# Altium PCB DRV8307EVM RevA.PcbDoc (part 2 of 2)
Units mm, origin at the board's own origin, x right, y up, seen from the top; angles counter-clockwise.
Board outline 87.73 x 75 mm, 2 copper layers (Top Layer, Bottom Layer), stack 1.575 mm thick; 84 components, 57 nets, 289 pads, 360 vias.
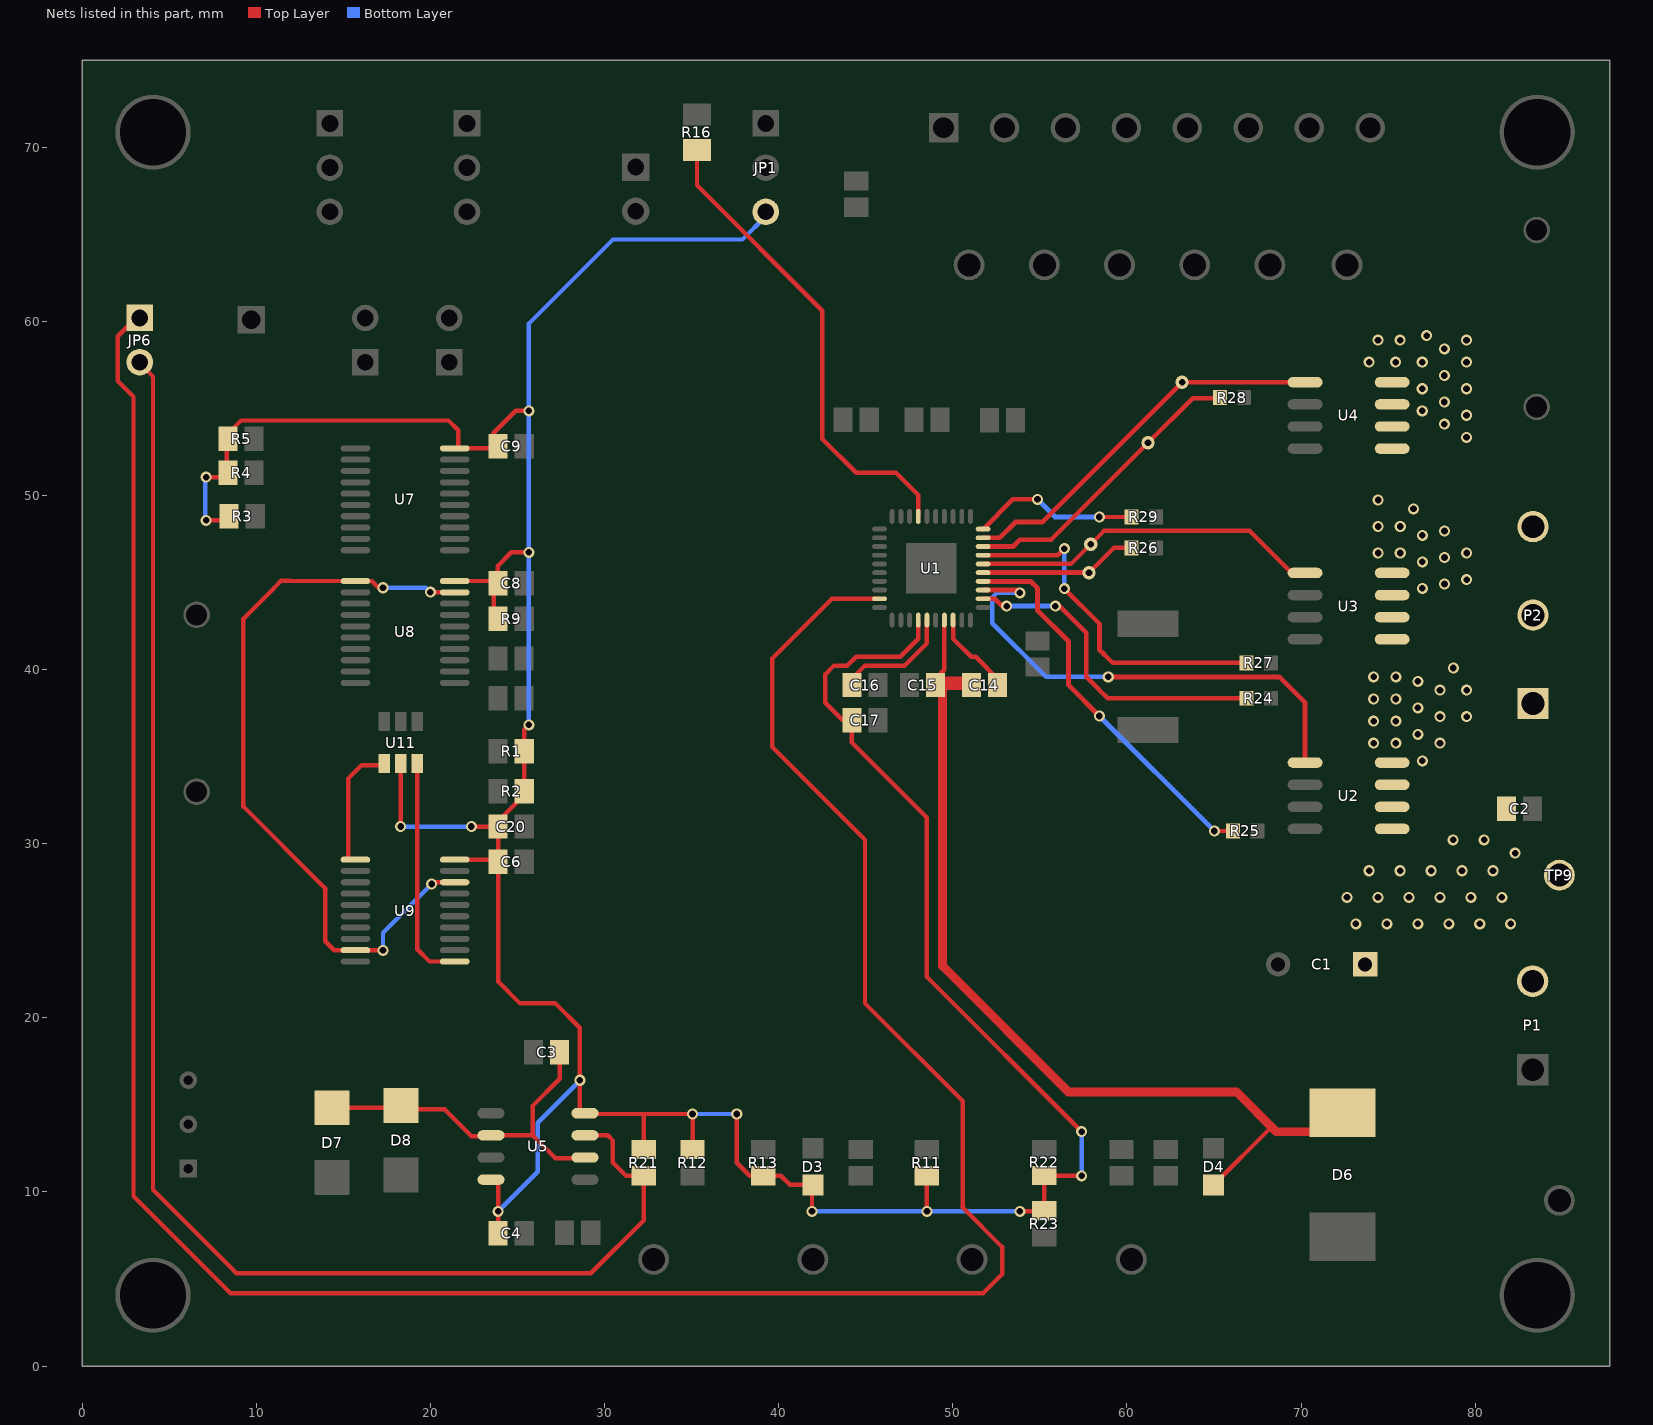
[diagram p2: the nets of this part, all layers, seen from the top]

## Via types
v1: diameter 0.635, hole 0.381, Top Layer to Bottom Layer, tented both sides, 350 vias
v2: diameter 0.635, hole 0.381, Top Layer to Bottom Layer, tented bottom, 5 vias
v3: diameter 0.762, hole 0.381, Top Layer to Bottom Layer, tented bottom, 4 vias
v4: diameter 0.635/0.635 (per signal layer), hole 0.381, Top Layer to Bottom Layer, tented both sides, 1 vias

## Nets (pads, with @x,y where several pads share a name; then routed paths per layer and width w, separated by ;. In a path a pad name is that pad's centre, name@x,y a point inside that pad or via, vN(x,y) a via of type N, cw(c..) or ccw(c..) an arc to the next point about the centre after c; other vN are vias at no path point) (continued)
NetU8_1: U8.1 U8.19 U9.9 U9.18 | length 43.9
  Top Layer w0.254: 13.959,27.432 13.959,24.395 14.467,23.887 U9.9@15.692,23.887 17.261,23.887 v1(17.272,23.876) ; 13.959,27.435 9.258,32.136 9.258,42.926 11.036,44.704 11.036,44.718 11.416,45.098 11.952,45.098 11.961,45.089 U8.1@15.692,45.089 16.633,45.089 17.018,44.704 v1(17.272,44.704) ; v1(19.99,44.45) 21.381,44.45 U8.19@21.392,44.439 ; v1(20.066,27.686) 20.167,27.787 U9.18@21.392,27.787
  Bottom Layer w0.254: v1@17.018,44.704 19.736,44.704 v1(19.99,44.45) ; v1(17.272,23.876) 17.272,24.892 v1(20.066,27.686)
NetU9_1: U9.1 U11.4 | length 7.1
  Top Layer w0.254: U9.1@15.279,29.087 15.279,33.742 16.041,34.505 17.233,34.505 U11.4@17.338,34.61
NetU9_11: U9.11 U11.6 | length 13.1
  Top Layer w0.254: U11.6@19.238,34.614 19.238,23.942 19.943,23.237 U9.11@21.392,23.237
PWM: JP6.1 U1.19 | length 152.4
  Top Layer w0.254: JP6.1@3.163,60.272 2.032,59.141 2.032,56.583 2.946,55.669 2.946,9.761 8.519,4.188 51.741,4.188 52.832,5.279 52.832,6.846 50.58,9.098 50.58,15.206 44.958,20.828 44.958,30.226 39.624,35.56 39.624,40.64 43.056,44.072 U1.19@45.791,44.072
PWM_X: JP6.2 R21.1 U5.7 | length 87.4
  Top Layer w0.254: JP6.2@3.163,57.732 4.064,56.83 4.064,10.126 8.856,5.334 29.21,5.334 32.258,8.382 R21.1@32.258,10.934 31.23,10.934 30.48,11.684 30.48,12.954 30.183,13.251 U5.7@28.565,13.251
THRES: C3.2 D7.1 D8.2 U5.2 U5.6 | length 21.1
  Top Layer w0.254: D7.1@14.349,14.838 18.335,14.838 18.433,14.74 20.82,14.74 22.352,13.208 U5.2@23.622,13.208 ; U5.2@23.765,13.251 25.865,13.251 ; C3.2@27.432,18.288 27.432,16.51 25.865,14.943 25.865,13.251 ; U5.6@28.702,11.938 27.178,11.938 25.865,13.251
U: P2.1 U1.33 U2.1 U2.5 U2.6 | length 28.6
  Top Layer w0.254: v1@53.692,44.572 v1(53.854,44.41)
  Top Layer w0.279: U1.33@51.741,44.572 v1@53.692,44.572 ; v2(58.928,39.584) 68.743,39.584 70.234,38.093 U2.1@70.234,34.662
  Bottom Layer w0.254: v1(53.854,44.41) 52.538,44.41 52.266,44.138 52.266,42.672 55.354,39.584 v2(58.928,39.584)
UHS_GATE: R24.1 U1.32 | length 19
  Top Layer w0.254: v1@52.838,43.648 v1(53.092,43.648) ; 58.403,38.845 58.894,38.354 R24.1@66.864,38.354
  Top Layer w0.279: U1.32@51.741,44.072 52.414,44.072 v1@52.838,43.648 ; v2(55.886,43.648) 56.14,43.648 57.664,42.124 57.664,39.584 58.403,38.845
  Bottom Layer w0.279: v1(53.092,43.648) v2(55.886,43.648)
ULS_GATE: R25.1 U1.34 | length 22.3
  Top Layer w0.254: v1(65.024,30.734) R25.1@66.102,30.734
  Top Layer w0.279: U1.34@51.741,45.072 54.462,45.072 54.87,44.664 54.87,43.394 56.648,41.616 56.648,39.11 v2(58.42,37.338)
  Bottom Layer w0.279: v2(58.42,37.338) v1@64.906,30.852
V: P2.2 U1.36 U3.1 U3.5 U3.6 | length 20.3
  Top Layer w0.254: U1.36@51.741,46.072 56.786,46.072 58.68,47.966 67.062,47.966 69.475,45.553 U3.1@70.234,45.553
  other v3: 57.918,47.204
VCP: C14.2 U1.28 | length 4.6
  Top Layer w0.254: U1.28@50.016,42.847 50.016,41.778 51.052,40.742 51.31,40.742 C14.2@52.614,39.438
VHS_GATE: R26.1 U1.35 | length 9.1
  Top Layer w0.254: v3(57.823,45.572) 59.241,46.99 R26.1@60.26,46.99
  Top Layer w0.279: U1.35@51.741,45.572 v3(57.823,45.572)
VINT: C16.2 U1.25 | length 6.9
  Top Layer w0.254: C16.2@43.902,39.184 44.951,40.234 47.242,40.234 48.516,41.508 U1.25@48.516,42.847
VLS_GATE: R27.1 U1.37 | length 20.2
  Top Layer w0.254: v2(56.407,44.65) 58.42,42.638 ; 58.694,40.874 59.182,40.386 R27.1@66.864,40.386
  Top Layer w0.279: U1.37@51.741,46.572 56.029,46.572 v1(56.407,46.95) ; 58.42,42.638 58.42,41.148 58.694,40.874
  Bottom Layer w0.254: v2(56.407,44.65) v1(56.407,46.95)
VM: C1.1 C2.1 C14.1 C15.1 D4.1 D6.2 P1.2 TP9.1 U1.27 U2.7 U2.8 U3.7 U3.8 U4.7 U4.8 | length 52.6
  Top Layer w0.254: C15.1@49.058,39.534 49.516,39.992 U1.27@49.516,42.847 ; C15.1@49.414,38.895 49.091,39.218 C15.1@49.414,39.541 ; D4.1@64.979,10.409 68.306,13.736
  Top Layer w0.508: C15.1@49.414,38.895 49.414,22.976 56.642,15.748 66.294,15.748 68.58,13.462 D6.2@71.12,13.462
  Top Layer w0.762: C15.1@49.091,39.218 C14.1@51.014,39.218
  other v1: 73.152,25.4 74.93,25.4 76.708,25.4 78.486,25.4 80.264,25.4 82.042,25.4 72.644,26.924 74.422,26.924 76.2,26.924 77.978,26.924 79.756,26.924 81.534,26.924 73.914,28.448 75.692,28.448 77.47,28.448 79.248,28.448 81.026,28.448 82.296,29.464 78.74,30.226 80.518,30.226 76.968,34.758 74.174,35.774 75.444,35.774 77.984,35.774 76.714,36.282 74.174,37.044 75.444,37.044 77.984,37.298 79.508,37.298 76.714,37.806 74.174,38.314 75.444,38.314 77.984,38.822 79.508,38.822 76.714,39.33 74.174,39.584 75.444,39.584 78.746,40.092 76.968,44.664 78.238,44.918 79.508,45.172 76.968,46.188 78.238,46.442 74.428,46.696 75.698,46.696 79.508,46.696 76.968,47.712 78.238,47.966 74.428,48.22 75.698,48.22 76.46,49.236 74.428,49.744 79.502,53.34 78.232,54.102 79.502,54.61 76.962,54.864 78.232,55.372 76.962,56.134 79.502,56.134 78.232,56.896 73.914,57.658 75.438,57.658 76.962,57.658 79.502,57.658 78.232,58.42 74.422,58.928 75.692,58.928 79.502,58.928 77.216,59.182
VREG: C4.2 C6.2 C8.2 C9.2 C17.2 C20.1 D3.1 JP1.3 R1.2 R2.2 R3.2 R4.2 R5.2 R9.2 R11.2 R12.2 R13.2 R21.2 R22.2 R23.2 U1.24 U5.4 U5.8 U7.20 U8.20 U9.20 U11.5 | length 209.3
  Top Layer w0.254: v1(7.112,48.573) 8.29,48.573 R3.2@8.374,48.657 ; v4(7.112,51.054) R4.2@8.311,51.054 ; R5.2@8.311,53.269 R4.2@8.311,51.054 ; R5.2@8.311,53.28 8.311,53.497 9.124,54.31 21.036,54.31 21.59,53.757 U7.20@21.59,52.832 ; R4.2@8.382,51.054 R4.2@8.311,51.054 ; v1(18.288,30.988) U11.5@18.288,34.614 ; U9.20@21.392,29.087 23.757,29.087 C6.2@23.888,28.956 ; U8.20@21.392,45.089 23.503,45.089 C8.2@23.634,44.958 ; U7.20@21.392,52.709 23.511,52.709 23.634,52.832 23.634,53.606 24.892,54.864 v1(25.654,54.864) ; v1(22.352,30.988) C20.1@23.888,30.988 23.888,31.303 25.388,32.803 R2.2@25.388,33.02 R1.2@25.388,35.306 25.388,36.564 v1(25.654,36.83) ; R9.2@23.634,42.926 C8.2@23.634,44.958 ; U5.4@23.7,10.646 U5.4@23.765,10.711 ; v1@23.876,8.89 v1(23.888,8.89) ; U5.4@23.876,10.668 23.888,10.656 v1(23.888,8.89) ; C4.2@23.881,7.62 C4.2@23.885,7.624 ; C4.2@23.888,7.62 v1(23.888,8.89) ; C20.1@23.888,30.492 C6.2@23.888,28.956 ; v1(25.654,46.736) 24.638,46.736 23.876,45.974 23.876,45.2 C8.2@23.634,44.958 ; U5.8@28.565,14.478 32.258,14.478 ; U5.8@28.63,14.586 28.565,14.521 28.565,16.405 v1(28.576,16.416) 28.576,19.43 27.178,20.828 25.146,20.828 23.888,22.086 C6.2@23.888,28.956 ; R21.2@32.258,12.434 32.258,14.478 ; R12.2@35.04,12.434 35.052,12.446 v1(35.052,14.478) 32.258,14.478 ; v1(37.592,14.478) 37.592,11.684 38.342,10.934 R13.2@39.116,10.934 40.12,10.934 40.645,10.409 41.91,10.409 41.912,10.407 v1(41.912,8.89) ; C17.2@43.954,37.084 44.196,36.842 44.196,35.814 48.516,31.494 48.516,22.352 57.404,13.464 v1(57.404,13.462) ; C17.2@44.252,37.128 43.644,37.128 42.67,38.102 42.67,39.726 43.178,40.234 43.94,40.234 44.448,40.742 46.988,40.742 48.016,41.77 U1.24@48.016,42.847 ; R11.2@48.514,10.934 48.516,10.932 v1(48.516,8.89) ; v1(53.854,8.89) 55.23,8.89 R23.2@55.258,8.918 R22.2@55.258,10.922 ; R22.2@55.258,10.946 R22.2@55.258,10.922 ; v1(57.404,10.922) R22.2@55.258,10.922
  Bottom Layer w0.254: v1@7.063,48.573 7.063,51.005 v4(7.112,51.054) ; v1(18.288,30.988) v1(22.352,30.988) ; v1(23.888,8.89) 26.162,11.164 26.162,13.97 28.576,16.384 v1(28.576,16.416) ; v1(25.654,36.83) v1(25.654,46.736) v1(25.654,54.864) 25.654,59.878 30.48,64.704 37.919,64.704 JP1.3@39.255,66.04 ; v1(35.052,14.478) v1(37.592,14.478) ; v1(41.912,8.89) v1(48.516,8.89) v1(53.854,8.89) ; v1(57.404,10.922) v1(57.404,13.462)
VSW: R16.1 U1.7 | length 27.7
  Top Layer w0.254: R16.1@35.306,69.85 35.307,67.819 42.507,60.618 42.507,53.251 44.45,51.308 46.736,51.308 48.016,50.028 U1.7@48.016,48.797
W: P2.3 U1.39 U4.1 U4.5 U4.6 | length 22.2
  Top Layer w0.279: U1.39@51.741,47.572 52.698,47.572 53.6,48.474 55.137,48.474 v3(63.169,56.506) 66.3,56.506 U4.1@70.234,56.506
WHS_GATE: R28.1 U1.38 | length 17.1
  Top Layer w0.254: 55.645,47.458 v3(61.214,53.027) 63.773,55.586 65.3,55.586 R28.1@65.34,55.626
  Top Layer w0.279: U1.38@51.741,47.072 53.468,47.072 53.854,47.458 55.645,47.458
WLS_GATE: R29.1 U1.40 | length 9.6
  Top Layer w0.254: v2(58.42,48.768) R29.1@60.26,48.768
  Top Layer w0.279: U1.40@51.741,48.072 53.453,49.784 v1(54.864,49.784)
  Bottom Layer w0.279: v1(54.864,49.784) 55.88,48.768 v2(58.42,48.768)
pads on no net: JP3.1 JP4.1 U1.8 U1.9 U1.10 U1.11 U1.12 U1.13 U1.14 U1.15 U1.23 U7.3 U7.8 U7.12 U7.17 U8.3 U8.8 U8.12 U8.17 U9.3 U9.4 U9.5 U9.6 U9.7 U9.8 U9.12 U9.13 U9.14 U9.15 U9.16 U9.17

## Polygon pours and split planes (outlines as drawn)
GND on Top Layer "Top GND plane" (solid, remove dead copper, pour order 5): 0,0 0,75 87.732,75 87.732,0
GND on Bottom Layer "Bottom GND plane" (solid, remove dead copper, pour order 7): 0,0 0,75 87.732,75 87.732,0

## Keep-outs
Keep-Out Layer:
  lines w0.5: -0.25,0 ccw(c0,0) 0,-0.25 ; -0.25,0 ccw(c0,0) 0,-0.25 ; -0.25,0 -0.25,75 ; -0.25,75 cw(c0,75) 0,75.25 ; -0.25,75 cw(c0,75) 0,75.25 ; 0,-0.25 87.732,-0.25 ; 0,75.25 87.732,75.25 ; 87.732,-0.25 ccw(c87.732,0) 87.982,0 ; 87.732,-0.25 ccw(c87.732,0) 87.982,0 ; 87.732,75.25 cw(c87.732,75) 87.982,75 ; 87.732,75.25 cw(c87.732,75) 87.982,75 ; 87.982,0 87.982,75
  text ".Layer_Name" at 14.656,-21.806 h1.52

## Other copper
Top Layer:
  region net VM: 75.917,54.948 79.878,52.72 79.845,59.671 78.206,59.709 75.559,59.686 73.495,59.671 73.495,56.683 74.42,54.983
  region net VM: 70.405,13.11 74.308,13.088 76.644,17.629 79.805,19.97 84.253,20.96 85.811,27.73 85.817,28.871 82.55,30.734 81.635,31.415 81.28,32.766 78.152,30.543 76.131,29.668 73.525,29.663 72.244,28.373 72.22,23.928 71.799,20.34 70.657,17.174
  region net W: 69.509,56.766 72.464,56.766 73.498,55.508 73.96,54.771 74.26,54.449 74.561,54.259 76.033,54.24 76.033,52.362 73.716,52.362 72.401,54.274 71.801,55.24 71.508,55.768 71.056,56.146 69.41,56.184
  region net V: 69.509,45.844 72.464,45.844 73.498,44.586 73.96,43.849 74.26,43.527 74.561,43.337 76.033,43.318 76.039,41.384 73.829,41.288 72.401,43.352 71.801,44.318 71.508,44.846 71.056,45.224 69.41,45.262
  region net U: 69.509,34.922 72.464,34.922 73.498,33.664 73.96,32.927 74.26,32.605 74.561,32.415 76.033,32.396 76.033,30.518 73.716,30.518 72.401,32.43 71.801,33.396 71.508,33.924 71.056,34.302 69.41,34.34
  region net VM: 74.573,44.015 74.246,44.233 73.502,45.476 73.509,51.082 79.876,48.102 79.899,44.781 76.027,43.996
  region net VM: 75.457,33.085 76.064,33.085 79.878,37.101 79.877,40.729 73.511,40.41 73.504,34.464 74.389,33.12
  region net ISENSE: 70.09,31.837 70.083,31.831 69.367,31.831 68.513,31.377 68.088,31.431 67.577,31.484 66.931,31.57 65.579,31.678 64.366,33.1 63.691,34.333 63.563,34.825 63.563,37.922 66.14,37.922 67.471,36.753 67.712,36.568 67.853,36.387 67.922,35.781 67.905,34.863 68.121,33.942 68.671,33.077 69.529,32.413
  region net ISENSE: 69.532,42.726 68.754,42.267 67.605,41.284 63.868,41.289 60.845,41.289 59.436,41.402 59.164,43.173 59.106,43.862 59.415,45.842 59.842,46.132 66.049,46.43 66.889,45.964 68.62,43.823 69.559,43.307
  region net ISENSE: 69.558,54.26 68.683,54.913 64.923,54.913 64.428,54.5 64.014,53.633 63.638,52.022 63.605,49.379 68.068,49.383 68.596,49.929 68.674,51.989 68.811,53.04 68.952,53.269 69.543,53.676
  region net U: 75.865,32.421 76.402,32.685 82.386,39.12 84.437,39.12 84.436,36.972 80.063,32.823 78.27,31.288 76.099,30.13 73.545,30.145 73.515,31.706
  region net V: 74.537,43.276 83.256,44.268 84.448,44.268 84.448,42.134 77.521,41.192 73.832,40.98
  region net W: 73.571,52.263 82.912,47.127 84.457,47.119 84.423,49.036 80.263,52.049 76.004,54.267 75.144,54.293 73.571,53.544
  text ".Layer_Name" at 14.656,-21.806 h1.52
Bottom Layer:
  region net VM: 73.487,59.69 73.487,28.899 79.875,28.899 79.875,59.69
  region net VM: 79.783,31.936 81.788,30.734 83.191,30.157 85.819,28.861 85.822,27.715 85.036,24.609 84.435,22.516 84.217,20.987 72.777,22.26 72.238,26.245 72.253,28.381 73.486,29.634
  region net ISENSE: 72.085,57.455 73.235,57.463 73.241,30.207 69.185,30.42 68.513,31.378 67.602,31.478 66.942,31.58 65.582,31.671 64.382,33.09 63.691,34.336 63.566,34.828 63.559,39.91 62.463,40.893 59.479,41.413 59.287,42.303 59.18,43.189 59.106,43.862 59.528,45.998 62.905,46.185 63.539,46.691 63.598,47.956 63.63,52.013 64.011,53.623 64.428,54.499 64.896,54.915 66.092,54.915 66.752,55.43 67.447,57.415
  text ".Layer_Name" at 14.656,-21.806 h1.52

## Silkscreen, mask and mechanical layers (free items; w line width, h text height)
Top Overlay:
  lines w0.254: 0.254,62.992 30.48,62.992 ; 0.762,54.356 28.956,54.356 29.718,55.118 29.718,74.676 ; 12.192,54.356 12.192,62.992 ; 30.226,62.992 46.99,62.992 47.722,63.724 47.722,74.72 ; 55.88,44.196 55.88,52.324 42.291,52.324 42.291,35.828 46.297,35.828 51.857,35.828 55.886,35.828 55.886,43.18
  text "HALL" at 76.184,70.584 h1.78
  text "S.E." at 9.144,70.358 h1.27
  text "CURRENT" at 41.91,69.85 h1.27
  text "DIFF" at 17.186,69.594 h1.27
  text "INVERT" at 7.366,69.342 h1.27
  text "[" at 11.684,69.088 h4.57
  text "]" at 40.894,69.088 h4.57
  text "]" at 16.097,69.026 h4.57
  text "[" at 19.737,69.026 h4.57
  text "INPUT" at 76.2,68.834 h1.78
  text "SINGLE" at 24.638,68.072 h1.27
  text "_" at 53.723,66.967 h1.4
  text "_" at 60.533,66.967 h1.4
  text "_" at 67.563,66.967 h1.4
  text "S.E." at 8.128,66.802 h1.27
  text "ENDED" at 24.638,66.802 h1.27
  text "]" at 23.622,66.548 h4.57
  text "HPWR" at 72.421,66.517 h1.27
  text "HGND" at 48.009,66.504 h1.27
  text "5V" at 34.434,66.378 h1.52
  text "W" at 52.343,66.356 h1.52
  text "W" at 55.8,66.356 h1.52
  text "V" at 59.533,66.356 h1.52
  text "V" at 62.996,66.356 h1.52
  text "U" at 66.58,66.356 h1.52
  text "U" at 69.999,66.356 h1.52
  text "+" at 57.172,66.284 h1.78
  text "+" at 63.988,66.284 h1.78
  text "+" at 70.974,66.284 h1.78
  text "]" at 33.274,65.905 h4.57
  text "[" at 36.322,65.905 h4.57
  text "NORMAL" at 5.334,65.786 h1.27
  text "[" at 10.668,65.786 h4.57
  text "HALL SIGNALS" at 12.7,63.5 h1.78
  text "HALL POWER" at 32.731,63.352 h1.78
  text "GND" at 8.535,61.43 h1.27
  text "PWM" at 5.08,59.69 h1.27
  text "INSTALLED" at 22.86,58.928 h1.27
  text "GND" at 78.134,58.928 h1.78
  text "IS LOW" at 22.86,57.912 h1.27
  text "W" at 71.571,57.359 h2.79
  text "SPEED_ADJ" at 5.08,57.15 h1.27
  text "W" at 62.738,57.15 h1.02
  text "SPEED" at 3.556,54.864 h1.78
  text "BRAKE" at 13.208,54.864 h1.78
  text "DIR" at 19.812,54.864 h1.78
  text "WHSG" at 59.944,53.594 h1.02
  text "DRV8307" at 45.734,50.546 h1.78
  text "WLSG" at 57.026,49.258 h1.02
  text "V" at 58.412,46.89 h1.02
  text "V" at 71.938,46.393 h2.79
  text "VHSG" at 58.385,45.26 h1.02
  text "VLSG" at 56.824,44.277 h1.02
  text "UHSG" at 56.332,43.311 h1.02
  text "U" at 57.937,39.232 h1.02
  text "GND" at 2.54,37.592 h1.78
  text "ULSG" at 56.364,36.235 h1.02
  text "U" at 71.999,35.582 h2.79
  text "VM" at 83.699,25.165 h1.78
  text "DRV8307EVM" at 32.512,22.098 h2.54
  text "REV.A" at 49.53,22.098 h2.54
  text "SPEED ADJUST" at 0.508,19.558 h2.03
  text "GND" at 83.147,11.441 h1.78
  text "VM" at 63.679,8.128 h2.03
  text "HALLOUT" at 28.706,2.641 h2.03
  text "FAULTn" at 38.932,2.652 h2.03
  text "LOCKn" at 48.109,2.641 h2.03
  text "ENABLE" at 56.628,2.64 h2.03
  text ".Layer_Name" at 14.656,-21.806 h1.52
Bottom Overlay:
  text ".Layer_Name" at 14.656,-21.806 h1.52
Top Paste:
  text ".Layer_Name" at 14.656,-21.806 h1.52
Bottom Paste:
  text ".Layer_Name" at 14.656,-21.806 h1.52
Top Solder:
  text ".Layer_Name" at 14.656,-21.806 h1.52
  text ".Layer_Name" at 14.656,-21.806 h1.52
Bottom Solder:
  text ".Layer_Name" at 14.656,-21.806 h1.52
Drill Guide:
  text ".Layer_Name" at 14.656,-21.806 h1.52
M1 Board Outline:
  the board outline again, w0.254
  text ".Layer_Name" at 14.656,-21.806 h1.52
M2 Board Dimensions:
  rectangle: 3.162,-10.427 12.687,-7.252
  rectangle: -0.013,-7.252 3.162,-4.077
  lines w0.178: -0.013,-7.252 25.387,-7.252 ; 3.162,-10.427 3.162,-4.077 ; 6.337,-10.427 6.337,-4.077 ; 12.687,-10.427 12.687,-4.077 ; 19.037,-10.427 19.037,-4.077 ; -0.013,-10.427 -0.013,-4.077 25.387,-4.077 25.387,-10.427 -0.013,-10.427
  lines w0.254: -0.013,-12.078 -0.013,-11.57 ; 1.511,-12.332 -0.013,-11.824 ; 1.511,-11.316 -0.013,-11.824 ; 6.187,-11.824 -0.013,-11.824 ; 19.188,-11.824 25.387,-11.824 ; 23.863,-12.332 25.387,-11.824 ; 23.863,-11.316 25.387,-11.824 ; 25.387,-12.078 25.387,-11.57
  text "25.4 (mm)" at 6.441,-12.738 h1.52
  text ".Layer_Name" at 14.656,-21.806 h1.52
M3 3D STEP Top:
  text ".Layer_Name" at 14.656,-21.806 h1.52
M4 3D STEP Bottom:
  text ".Layer_Name" at 14.656,-21.806 h1.52
M5 Assembly Top:
  lines w0.254: -7.417,-23.626 160.223,-23.626 ; -7.417,-18.462 160.274,-18.462 ; -7.417,-13.297 -7.417,-28.791 94.31,-28.791 160.274,-28.791 160.274,-13.297 -7.404,-13.297 -7.404,-28.791 32.614,-28.791 ; 55.194,-28.791 55.194,-13.297 ; 87.376,-18.462 87.376,-13.297 ; 108.712,-18.462 108.712,-13.297 ; 124.511,-28.956 124.511,-23.804
  text "COMPONENTS MARKED 'DNP' SHOULD NOT BE POPULATED." at 29.299,-8.09 h1.52
  text "ASSEMBLY VARIANT:" at 29.286,-11.024 h1.52
  text ".VariantName" at 55.601,-11.024 h1.52
  text "PCB VIEWED FROM TOP SIDE" at -5.804,-16.654 h1.52
  text "BOARD #:" at 57.099,-16.654 h1.52
  text ".PRJ_Number" at 70.955,-16.654 h1.52
  text "REV:" at 92.405,-16.654 h1.52
  text ".PCB_Rev" at 99.809,-16.654 h1.52
  text "SVN REV:" at 113.69,-16.654 h1.52
  text ".VersionControl_RevNumber" at 126.543,-16.654 h1.52
  text "IGNORE ->" at -5.804,-21.806 h1.52
  text "PLOT NAME =" at -5.804,-27.034 h1.52
  text ".plot_File_Name" at 14.656,-27.034 h1.52
  text "GENERATED    :" at 57.15,-27.034 h1.52
  text ".Print_Date" at 79.235,-27.034 h1.52
  text ".Print_Time" at 97.752,-27.034 h1.52
  text "TEXAS INSTRUMENTS" at 129.87,-27.034 h1.52
M6 Assembly Bottom:
  lines w0.254: -7.429,-18.474 160.261,-18.474 ; -7.379,-23.639 160.261,-23.639 ; 28.334,-28.969 28.334,-23.817 ; 44.133,-18.474 44.133,-13.31 ; 65.468,-18.474 65.468,-13.31 ; 97.65,-28.804 97.65,-13.31 ; 120.231,-28.804 160.249,-28.804 160.249,-13.31 -7.429,-13.31 -7.429,-28.804 58.534,-28.804 160.261,-28.804 160.261,-13.31
  text "COMPONENTS MARKED 'DNP' SHOULD NOT BE POPULATED." at 154.991,-8.077 h1.52
  text ".VariantName" at 128.473,-11.024 h1.52
  text "ASSEMBLY VARIANT:" at 154.864,-11.024 h1.52
  text ".VersionControl_RevNumber" at 26.302,-16.667 h1.52
  text "SVN REV:" at 39.154,-16.667 h1.52
  text ".PCB_Rev" at 53.035,-16.667 h1.52
  text "REV:" at 60.439,-16.667 h1.52
  text ".PRJ_Number" at 81.89,-16.667 h1.52
  text "BOARD #:" at 95.745,-16.667 h1.52
  text "PCB VIEWED FROM BOTTOM SIDE" at 158.648,-16.667 h1.52
  text "IGNORE ->" at 64.715,-21.806 h1.52
  text "TEXAS INSTRUMENTS" at 22.974,-27.047 h1.52
  text ".Print_Time" at 55.093,-27.047 h1.52
  text ".Print_Date" at 73.609,-27.047 h1.52
  text "GENERATED    :" at 95.694,-27.047 h1.52
  text ".plot_File_Name" at 138.189,-27.047 h1.52
  text "PLOT NAME =" at 158.648,-27.047 h1.52
M9 Title Sheet:
  drawing of 57 lines, arcs and shapes, not listed
  text "1" at 18.792,204.127 h1.78
  text "2" at 82.182,204.127 h1.78
  text "3" at 145.411,204.127 h1.78
  text "4" at 209.08,204.127 h1.78
  text "5" at 272.555,204.127 h1.78
  text "6" at 336.182,204.127 h1.78
  text "A" at -10.579,175.095 h1.78
  text "A" at 365.341,175.095 h1.78
  text "B" at -10.579,114.643 h1.78
  text "B" at 365.341,114.643 h1.78
  text "C" at -10.579,54.318 h1.78
  text "C" at 365.341,54.318 h1.78
  text "PROJECT TITLE:" at 288.125,7.048 h1.14
  text ".PRJ_Title" at 289.395,3.662 h1.78
  text "DESIGNED FOR:" at 288.125,-0.597 h1.14
  text ".PRJ_Customer" at 289.395,-4.153 h1.78
  text "D" at -10.579,-5.88 h1.78
  text "D" at 365.341,-5.88 h1.78
  text "FILE NAME:" at 288.125,-8.217 h1.14
  text ".PCB_File_Name_No_Path" at 289.395,-11.265 h1.78
  text "Texas Instruments (TI) and/or its licensors do not warrant the accuracy or completeness of this specification" at 161.9,-15.376 h1.14
  text "ENGINEER:" at 288.125,-15.583 h1.14
  text "LAYOUT BY:" at 326.352,-15.583 h1.14
  text "or any information contained therein. TI and/or its licensors do not warrant that this design will meet" at 160.757,-18.237 h1.14
  text ".PRJ_Engineer" at 289.395,-19.52 h1.78
  text ".PCB_Layout" at 327.635,-19.52 h1.78
  text "the specifications, will be suitable for your application or fit for any particular purpose, or will operate in" at 160.757,-21.099 h1.14
  text ".Layer_Name" at 14.656,-21.806 h1.52
  text "ALTIUM DESIGNER VERSION:" at 326.352,-23.457 h1.14
  text "an implementation. TI and/or its licensors do not warrant that the design is production worthy. You should" at 160.757,-23.961 h1.14
  text "completely validate and test your design implementation to confirm the system functionality for your application." at 161.9,-26.822 h1.14
  text ".print_Scale" at 289.395,-26.843 h1.78
  text ".Application_BuildNumber" at 327.635,-26.843 h1.78
  text "1" at 18.792,-32.093 h1.78
  text "2" at 82.182,-32.093 h1.78
  text "3" at 145.411,-32.093 h1.78
  text "4" at 209.08,-32.093 h1.78
  text "5" at 272.555,-32.093 h1.78
  text "6" at 336.182,-32.093 h1.78
M10 Fab Notes:
  drawing of 213 lines, arcs and shapes, not listed
  text "DESIGN INFORMATION" at 314.478,172.974 h1.52
  text "(REFER ALSO ARRAY/PANEL PROFILING INFORMATION)" at 305.294,168.866 h1.52
  text "BOARD SIZE" at 287.87,168.758 h1.52
  text "3463.4MIL" at 299.613,165.511 h1.52
  text "X" at 312.457,165.511 h1.52
  text "2952.8MIL" at 318.333,165.511 h1.52
  text "Number of Layers :" at 298.106,160.503 h1.52
  text "2" at 325.914,160.249 h1.52
  text "MIN. TRACK WIDTH:" at 298.106,156.972 h1.52
  text "10" at 325.374,156.972 h1.52
  text "MIL" at 329.881,156.972 h1.52
  text "MIN. CLEARANCE:" at 298.106,153.619 h1.52
  text "8" at 325.951,153.619 h1.52
  text "MIL" at 329.881,153.619 h1.52
  text "MIN. VIA PAD SIZE:" at 298.106,150.266 h1.52
  text "25" at 325.189,150.266 h1.52
  text "MIL" at 329.881,150.266 h1.52
  text "5" at 325.882,146.812 h1.52
  text "MIL" at 329.946,146.812 h1.52
  text "MIN. ANNULAR RING:" at 298.107,146.559 h1.52
  text "PER" at 294.824,143.561 h1.52
  text "IPC-D-275 CLASS 2 LEVEL C" at 300.412,143.561 h1.52
  text "MIL, HOLES" at 338.213,140.709 h1.52
  text "+/-" at 328.244,140.691 h1.52
  text "+/-" at 349.936,140.691 h1.52
  text "REGISTRATION TOLERANCES:" at 289.744,140.564 h1.52
  text "METAL" at 320.218,140.564 h1.52
  text "5" at 334.853,140.564 h1.52
  text "3" at 356.012,140.564 h1.52
  text "MIL" at 358.964,140.564 h1.52
  text "MATERIAL:" at 287.844,135.243 h1.52
  text "FR-4 High Tg" at 312.9,131.679 h1.52
  text "FR-408" at 298.538,131.461 h1.52
  text "X" at 309.003,131.461 h1.52
  text "OTHER" at 336.333,131.461 h1.52
  text "62 MIL (1.6mm) +/-10%" at 306.668,127.328 h1.52
  text "THICKNESS:" at 289.744,127.219 h1.52
  text "X" at 303.413,127.219 h1.52
  text "OTHER" at 339.305,127.219 h1.52
  text "TOLERANCE:" at 289.744,123.206 h1.52
  text "X" at 311.062,123.206 h1.52
  text "ANSI IPC-6012 TYPE 3 CLASS 2" at 315.81,123.206 h1.52
  text "OTHER +/-" at 315.81,119.244 h1.52
  text "BOW & TWIST:" at 289.744,115.256 h1.52
  text "X" at 311.062,115.256 h1.52
  text "ANSI IPC-6012 TYPE 3 CLASS 2" at 315.81,115.256 h1.52
  text "OTHER +/-" at 315.81,111.23 h1.52
  text "COPPER THICKNESS (FINISHED):" at 287.844,107.788 h1.52
  text "1.4MIL (1oz)" at 310.196,103.909 h1.52
  text "2MIL (1.4oz)" at 329.678,103.909 h1.52
  text "2.8MIL (2oz)" at 348.144,103.909 h1.52
  text "OUTER:" at 296.912,103.801 h1.52
  text "X" at 326.39,103.632 h1.52
  text "1.4MIL (1oz)" at 310.196,99.922 h1.52
  text "2.8MIL (2oz)" at 329.678,99.922 h1.52
  text "N/A" at 348.132,99.931 h1.52
  text "INNER SIGNAL:" at 289.57,99.813 h1.52
  text "X" at 344.932,99.822 h1.52
  text "DRILLING:" at 287.844,96.282 h1.52
  text "REFERENCE:" at 289.744,93.31 h1.52
  text "X" at 306.209,93.31 h1.52
  text "AS SHOWN" at 310.958,93.31 h1.52
  text "X" at 329.094,93.31 h1.52
  text "NC_DRILL FILES" at 332.574,93.31 h1.52
  text "PTH MIN COPPER THICKNESS:" at 289.744,89.297 h1.52
  text "X" at 324.039,89.297 h1.52
  text "1MIL" at 327.519,89.297 h1.52
  text "OTHER" at 340.143,89.297 h1.52
  text "BOARD FINISH:" at 287.844,85.259 h1.52
  text "SILKSCREEN:" at 291.787,82.261 h1.52
  text "X" at 315.886,82.261 h1.52
  text "TOP" at 319.086,82.261 h1.52
  text "BOTTOM" at 332.066,82.261 h1.52
  text "SILKSCREEN COLOR:" at 291.787,78.02 h1.52
  text "X" at 315.86,78.02 h1.52
  text "WHITE" at 319.086,78.02 h1.52
  text "OTHER" at 332.066,78.02 h1.52
  text "SOLDER RESIST COLOR:" at 291.787,73.702 h1.52
  text "X" at 306.208,69.658 h1.52
  text "GREEN" at 309.434,69.658 h1.52
  text "BLUE" at 324.446,69.658 h1.52
  text "OTHER" at 338.111,69.658 h1.52
  text "IMMERSION GOLD (ENIG)" at 314.794,64.87 h1.52
  text "ENEPIG" at 348.767,64.786 h1.52
  text "SURFACE FINISH:" at 287.844,64.761 h1.52
  text "X" at 310.045,64.761 h1.52
  text "IMM. TIN/SILVER OR EQUIV" at 296.215,60.773 h1.52
  text "OTHER" at 332.574,60.773 h1.52
  text "ARRAY/PANEL:" at 287.844,56.226 h1.52
  text "CUT AND TRIM PER MECH LAYER 1" at 314.794,56.118 h1.52
  text "N.C. ROUTE" at 314.794,52.264 h1.52
  text "X" at 332.04,52.264 h1.52
  text "V. SCORE" at 336.79,52.264 h1.52
  text "CERTIFICATION:" at 287.844,48.784 h1.52
  text "MATERIALS AND WORKMANSHIP FOR ALL PCBS" at 306.259,48.784 h1.52
  text "TO MEET OR EXCEED THE REQUIREMENTS OF:" at 306.259,46.295 h1.52
  text "X" at 296.773,42.828 h1.52
  text "ANSI IPC-A-600F CLASS ->" at 300.303,42.828 h1.52
  text "X" at 341.935,42.828 h1.52
  text "2" at 344.956,42.828 h1.52
  text "1" at 336.955,42.79 h1.52
  text "3" at 353.948,42.79 h1.52
  text "X" at 296.825,38.777 h1.52
  text "UL 94V-0" at 300.303,38.777 h1.52
  text "X" at 317.45,38.777 h1.52
  text "RoHS" at 320.928,38.777 h1.52
  text "OTHER" at 337.296,38.777 h1.52
  text "PER ORDER" at 347.381,38.777 h1.52
  text "ADDITIONAL REQUIREMENTS:" at 287.844,35.195 h1.52
  text "MICROSECTION:" at 289.744,32.274 h1.52
  text "YES" at 312.749,32.274 h1.52
  text "REQUIRED" at 334.631,28.308 h1.52
  text "BARE BOARD ELEC. TEST:" at 289.744,28.236 h1.52
  text "NONE" at 322.909,28.236 h1.52
  text "PER ORDER" at 349.668,28.236 h1.52
  text "X" at 346.202,28.194 h1.52
  text "MANUFACTURER'S UL:" at 289.744,24.248 h1.52
  text "RAIL" at 319.353,24.139 h1.52
  text "METAL" at 331.845,24.139 h1.52
  text "X" at 341.376,24.13 h1.52
  text "SILK" at 344.842,24.139 h1.52
  text ".Layer_Name" at 14.656,-21.806 h1.52
M11 Gerber Information:
  lines w0.254: -7.417,-23.626 160.223,-23.626 ; -7.417,-18.462 160.274,-18.462 ; -7.417,-13.297 -7.417,-28.791 94.31,-28.791 160.274,-28.791 160.274,-13.297 -7.404,-13.297 -7.404,-28.791 32.614,-28.791 ; 55.194,-28.791 55.194,-13.297 ; 87.376,-18.462 87.376,-13.297 ; 108.712,-18.462 108.712,-13.297 ; 124.511,-28.956 124.511,-23.804
  text "ALL ARTWORK VIEWED FROM TOP SIDE" at -5.804,-16.654 h1.52
  text "BOARD #:" at 57.099,-16.654 h1.52
  text ".PRJ_Number" at 70.955,-16.654 h1.52
  text "REV:" at 92.405,-16.654 h1.52
  text ".PCB_Rev" at 99.809,-16.654 h1.52
  text "SVN REV:" at 113.69,-16.654 h1.52
  text ".VersionControl_RevNumber" at 126.543,-16.654 h1.52
  text "LAYER NAME =" at -5.804,-21.806 h1.52
  text "PLOT NAME =" at -5.804,-27.034 h1.52
  text ".plot_File_Name" at 14.656,-27.034 h1.52
  text "GENERATED    :" at 57.15,-27.034 h1.52
  text ".Print_Date" at 79.235,-27.034 h1.52
  text ".Print_Time" at 97.752,-27.034 h1.52
  text "TEXAS INSTRUMENTS" at 129.87,-27.034 h1.52
M12 Stackup:
  lines w0.152: 288.544,189.484 353.314,189.484 ; 288.544,192.136 353.314,192.136 ; 287.02,177.165 ccw(c287.884,177.165) 287.884,176.301 353.974,176.301 ccw(c353.974,177.165) 354.838,177.165 354.838,195.097 ccw(c353.974,195.097) 353.974,195.961 287.884,195.961 ccw(c287.884,195.097) 287.02,195.097 287.02,177.165
  text "The Stackup Legend below this is static." at 294.78,200.012 h1.52
  text "If you change the stackup, update the Legend." at 295.034,197.726 h1.52
  text "Layer Stack Up Detail for: Ref_Design.PcbDoc" at 288.544,192.966 h1.45
  text "Layer" at 288.544,191.145 h0.61
  text "Gerber" at 311.298,191.145 h0.61
  text "Copper" at 325.611,191.145 h0.61
  text "Dielectric" at 340.92,191.145 h0.61
  text "Name" at 288.544,189.926 h0.61
  text "Document" at 311.298,189.926 h0.61
  text "Thickness" at 325.611,189.926 h0.61
  text "Material" at 340.92,189.926 h0.61
  text "Top Solder Mask" at 288.544,187.565 h0.86
  text "(.GTS)" at 311.298,187.565 h0.86
  text "Solder Resist" at 340.92,187.565 h0.86
  text "Top Layer" at 288.544,185.107 h0.86
  text "(.GTL)" at 311.298,185.107 h0.86
  text "1.4mil" at 325.611,185.107 h0.86
  text "FR-4" at 340.92,183.879 h0.86
  text "Bottom Layer" at 288.544,182.65 h0.86
  text "(.GBL)" at 311.298,182.65 h0.86
  text "1.4mil" at 325.611,182.65 h0.86
  text "Bottom Solder Mask" at 288.544,180.192 h0.86
  text "(.GBS)" at 311.298,180.192 h0.86
  text "Solder Resist" at 340.92,180.192 h0.86
  text ".Layer_Name" at 14.656,-21.806 h1.52
M13 Component Bodies Top:
  text ".Layer_Name" at 14.656,-21.806 h1.52
M14 Component Bodies Bottom:
  text ".Layer_Name" at 14.656,-21.806 h1.52
M15 Courtyards Top:
  text ".Layer_Name" at 14.656,-21.806 h1.52
M16 Courtyards Bottom:
  text ".Layer_Name" at 14.656,-21.806 h1.52
Drill Drawing:
  text ".Layer_Name" at 14.656,-21.806 h1.52

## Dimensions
0,0 to 0,75 on M2 Board Dimensions
0,0 to 87.732,0 on M2 Board Dimensions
